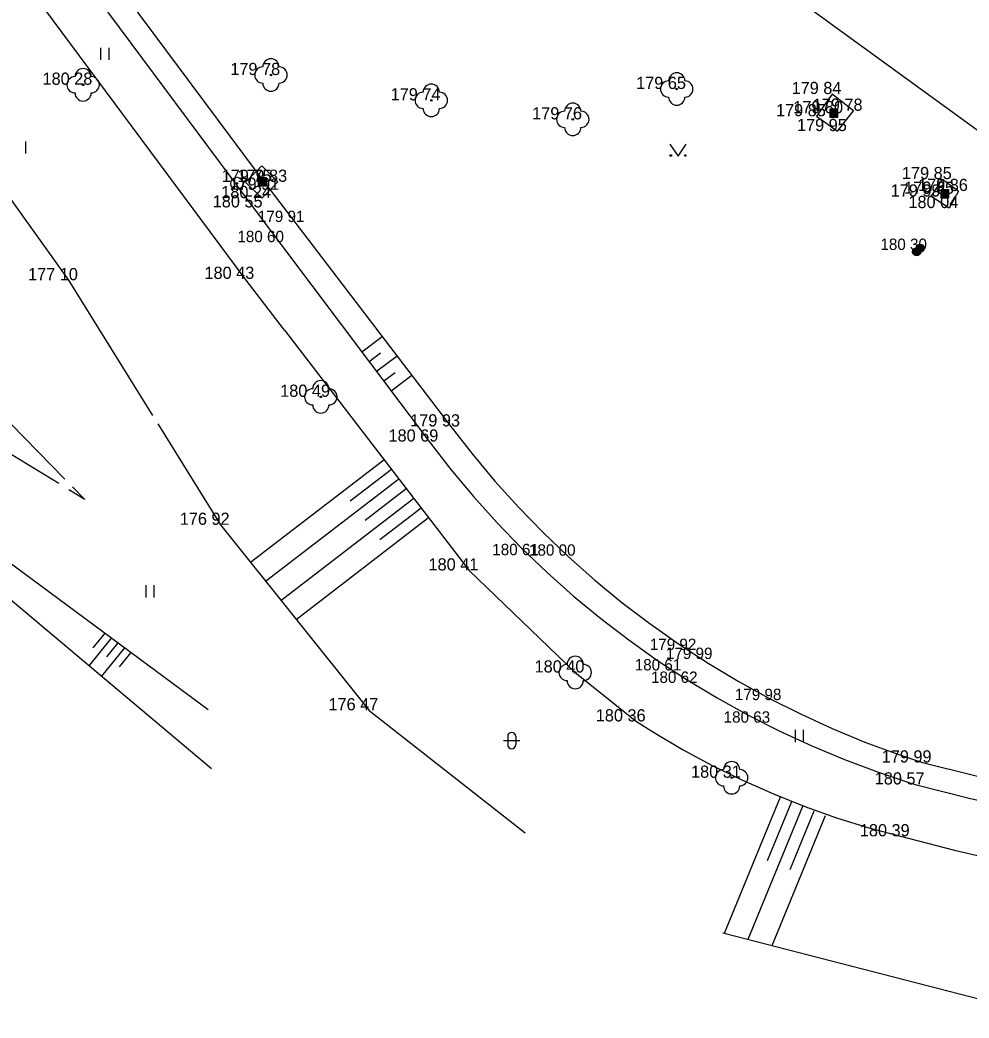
# Model space of a CAD drawing. Extents: x -537755 to -537431, y -1180722 to -1180510.
# Drawn here: x -537587.3 to -537528.9, y -1180712.7 to -1180651.3 of the extents above; entities that cross this region are included whole.
import ezdxf

# ---------------------------------------------------------------- set-up
doc = ezdxf.new("R2010")
doc.units = 0
for name, color, linetype in [('Vrstva 1', 7, 'Continuous'), ('Vrstva 11', 7, 'Continuous'), ('Vrstva 14', 7, 'Continuous'), ('Vrstva 15', 7, 'Continuous'), ('Vrstva 21', 7, 'Continuous'), ('Vrstva 22', 7, 'Continuous'), ('Vrstva 25', 7, 'Continuous'), ('Vrstva 3', 7, 'Continuous'), ('Vrstva 36', 7, 'Continuous'), ('Vrstva 4', 7, 'Continuous'), ('Vrstva 7', 7, 'Continuous')]:
    doc.layers.add(name, color=color, linetype=linetype)

msp = doc.modelspace()

# ---------------------------------------------------------------- linework, layer by layer
at = {"layer": 'Vrstva 1'}
for p, q in [((-537571.83, -1180654.66), (-537571.83, -1180654.66)), ((-537583.39, -1180655.26), (-537583.39, -1180655.26)), ((-537546.85, -1180655.52), (-537546.85, -1180655.52)), ((-537537.28, -1180655.83), (-537537.28, -1180655.83)), ((-537561.96, -1180656.22), (-537561.96, -1180656.22)), ((-537537.18, -1180657.01), (-537537.18, -1180657.01)), ((-537537.17, -1180657.03), (-537537.17, -1180657.03)), ((-537537.16, -1180657.03), (-537537.16, -1180657.03)), ((-537535.98, -1180656.86), (-537535.98, -1180656.86)), ((-537553.25, -1180657.39), (-537553.25, -1180657.39)), ((-537538.24, -1180657.2), (-537538.24, -1180657.2)), ((-537536.95, -1180658.11), (-537536.95, -1180658.11)), ((-537572.4, -1180661.25), (-537572.4, -1180661.25)), ((-537572.38, -1180661.27), (-537572.38, -1180661.27)), ((-537572.36, -1180661.24), (-537572.36, -1180661.24)), ((-537571.4, -1180661.235), (-537571.4, -1180661.235)), ((-537530.49, -1180661.07), (-537530.49, -1180661.07)), ((-537571.885, -1180661.727), (-537571.885, -1180661.727)), ((-537530.35, -1180661.97), (-537530.35, -1180661.97)), ((-537530.34, -1180661.92), (-537530.34, -1180661.92)), ((-537530.34, -1180661.97), (-537530.34, -1180661.97)), ((-537529.5, -1180661.8), (-537529.5, -1180661.8)), ((-537572.388, -1180662.237), (-537572.388, -1180662.237)), ((-537531.18, -1180662.14), (-537531.18, -1180662.14)), ((-537572.913, -1180662.812), (-537572.913, -1180662.812)), ((-537530.09, -1180662.85), (-537530.09, -1180662.85)), ((-537570.3, -1180663.71), (-537570.3, -1180663.71)), ((-537571.56, -1180664.95), (-537571.56, -1180664.95)), ((-537531.98, -1180665.43), (-537531.98, -1180665.43)), ((-537531.98, -1180665.45), (-537531.98, -1180665.45)), ((-537531.98, -1180665.53), (-537531.98, -1180665.53)), ((-537531.94, -1180665.49), (-537531.94, -1180665.49)), ((-537584.28, -1180667.29), (-537584.28, -1180667.29)), ((-537573.42, -1180667.21), (-537573.42, -1180667.21)), ((-537568.76, -1180674.47), (-537568.76, -1180674.47)), ((-537560.758, -1180676.295), (-537560.758, -1180676.295)), ((-537562.094, -1180677.223), (-537562.094, -1180677.223)), ((-537583.28, -1180680.79), (-537583.28, -1180680.79)), ((-537574.94, -1180682.35), (-537574.94, -1180682.35)), ((-537555.87, -1180684.22), (-537555.87, -1180684.22)), ((-537553.61, -1180684.25), (-537553.61, -1180684.25)), ((-537559.63, -1180685.16), (-537559.63, -1180685.16)), ((-537546.176, -1180690.057), (-537546.176, -1180690.057)), ((-537545.18, -1180690.61), (-537545.18, -1180690.61)), ((-537553.1, -1180691.44), (-537553.1, -1180691.44)), ((-537547.103, -1180691.315), (-537547.103, -1180691.315)), ((-537546.1, -1180692.08), (-537546.1, -1180692.08)), ((-537540.94, -1180693.14), (-537540.94, -1180693.14)), ((-537565.79, -1180693.77), (-537565.79, -1180693.77)), ((-537549.334, -1180694.452), (-537549.334, -1180694.452)), ((-537541.63, -1180694.53), (-537541.63, -1180694.53)), ((-537547.66, -1180695.08), (-537547.66, -1180695.08)), ((-537531.733, -1180696.981), (-537531.733, -1180696.981)), ((-537543.47, -1180697.92), (-537543.47, -1180697.92)), ((-537532.164, -1180698.334), (-537532.164, -1180698.334)), ((-537539.05, -1180699.72), (-537539.05, -1180699.72)), ((-537533.08, -1180701.525), (-537533.08, -1180701.525))]:
    msp.add_line(p, q, dxfattribs=at)
at = {"layer": 'Vrstva 11'}
msp.add_line((-537543.39, -1180647.11), (-537522, -1180662.66), dxfattribs=at)
msp.add_lwpolyline([(-537572.388, -1180662.237), (-537571.885, -1180661.727), (-537571.4, -1180661.235), (-537572.397, -1180660.252), (-537572.732, -1180660.592), (-537573.385, -1180661.254), (-537572.388, -1180662.237)], dxfattribs=at)
at = {"layer": 'Vrstva 14'}
for p, q in [((-537573.42, -1180667.21), (-537593.09, -1180640.69)), ((-537583.28, -1180646.46), (-537572.732, -1180660.592)), ((-537584.444, -1180647.34), (-537572.913, -1180662.812)), ((-537594.91, -1180652.5), (-537584.28, -1180667.29)), ((-537572.732, -1180660.592), (-537571.885, -1180661.727)), ((-537571.885, -1180661.727), (-537560.758, -1180676.295)), ((-537572.913, -1180662.812), (-537562.094, -1180677.223)), ((-537584.28, -1180667.29), (-537579.119, -1180675.612)), ((-537570.989, -1180670.374), (-537573.42, -1180667.21)), ((-537593.74, -1180670.11), (-537584.511, -1180679.533)), ((-537570.989, -1180670.374), (-537559.63, -1180685.16)), ((-537584.89, -1180679.808), (-537598.82, -1180671.31)), ((-537578.792, -1180676.139), (-537574.94, -1180682.35)), ((-537583.28, -1180680.79), (-537584.269, -1180680.186)), ((-537584.038, -1180680.016), (-537583.28, -1180680.79)), ((-537574.94, -1180682.35), (-537565.79, -1180693.77)), ((-537592.06, -1180683.41), (-537575.48, -1180697.36)), ((-537575.7, -1180693.73), (-537588.89, -1180683.98)), ((-537548.506, -1180688.433), (-537546.738, -1180689.681)), ((-537549.805, -1180689.438), (-537548.031, -1180690.695)), ((-537565.79, -1180693.77), (-537556.18, -1180701.31)), ((-537539.242, -1180693.992), (-537537.275, -1180694.893)), ((-537540.513, -1180695.047), (-537538.54, -1180695.958)), ((-537535.03, -1180700.998), (-537533.08, -1180701.525)), ((-537544.01, -1180707.46), (-537523.671, -1180712.712))]:
    msp.add_line(p, q, dxfattribs=at)
for points in [[(-537560.758, -1180676.295), (-537559.43, -1180678.003), (-537558.04, -1180679.662), (-537556.59, -1180681.267), (-537555.082, -1180682.818)], [(-537562.094, -1180677.223), (-537560.762, -1180678.941), (-537559.368, -1180680.608), (-537557.913, -1180682.223), (-537556.4, -1180683.783)], [(-537555.082, -1180682.818), (-537553.517, -1180684.312), (-537551.898, -1180685.747), (-537550.227, -1180687.122), (-537548.506, -1180688.433)], [(-537556.4, -1180683.783), (-537554.83, -1180685.287), (-537553.206, -1180686.732), (-537551.53, -1180688.116), (-537549.805, -1180689.438)], [(-537559.63, -1180685.16), (-537553.1, -1180691.44)], [(-537546.738, -1180689.681), (-537544.925, -1180690.862), (-537543.07, -1180691.975), (-537541.175, -1180693.019), (-537539.242, -1180693.992)], [(-537548.031, -1180690.695), (-537546.213, -1180691.886), (-537544.352, -1180693.009), (-537542.452, -1180694.063), (-537540.513, -1180695.047)], [(-537553.1, -1180691.44), (-537549.334, -1180694.452)], [(-537549.334, -1180694.452), (-537548.275, -1180695.122), (-537546.487, -1180696.177), (-537544.66, -1180697.163), (-537542.796, -1180698.077)], [(-537537.275, -1180694.893), (-537535.276, -1180695.72), (-537533.248, -1180696.473), (-537531.733, -1180696.981)], [(-537538.54, -1180695.958), (-537536.534, -1180696.797), (-537534.499, -1180697.56), (-537532.438, -1180698.249), (-537532.164, -1180698.334)], [(-537531.733, -1180696.981), (-537528.51, -1180697.785), (-537525.268, -1180698.511), (-537522.01, -1180699.158)], [(-537542.796, -1180698.077), (-537540.898, -1180698.919), (-537538.969, -1180699.687), (-537537.012, -1180700.381), (-537535.03, -1180700.998)], [(-537532.164, -1180698.334), (-537528.761, -1180699.188), (-537525.339, -1180699.965)], [(-537533.08, -1180701.525), (-537529.747, -1180702.38), (-537526.396, -1180703.158)]]:
    msp.add_lwpolyline(points, dxfattribs=at)
at = {"layer": 'Vrstva 15'}
for p, q in [((-537564.975, -1180670.773), (-537566.229, -1180671.715)), ((-537565.079, -1180671.79), (-537565.779, -1180672.315)), ((-537564.065, -1180671.966), (-537565.329, -1180672.914)), ((-537564.179, -1180672.989), (-537564.878, -1180673.514)), ((-537563.154, -1180673.158), (-537564.428, -1180674.114)), ((-537573.092, -1180684.656), (-537564.87, -1180678.339)), ((-537566.948, -1180680.88), (-537564.413, -1180678.933)), ((-537572.154, -1180685.827), (-537563.956, -1180679.528)), ((-537566.033, -1180682.07), (-537563.499, -1180680.123)), ((-537571.216, -1180686.998), (-537563.042, -1180680.718)), ((-537565.12, -1180683.26), (-537562.585, -1180681.312)), ((-537570.278, -1180688.168), (-537562.129, -1180681.907)), ((-537582.06, -1180689.029), (-537582.785, -1180689.923)), ((-537581.659, -1180689.325), (-537583.025, -1180691.012)), ((-537581.256, -1180689.623), (-537581.941, -1180690.468)), ((-537580.853, -1180689.921), (-537582.259, -1180691.656)), ((-537580.452, -1180690.218), (-537581.166, -1180691.1)), ((-537543.914, -1180707.485), (-537540.469, -1180699.097)), ((-537541.263, -1180703.005), (-537539.776, -1180699.382)), ((-537542.448, -1180707.863), (-537539.082, -1180699.667)), ((-537539.876, -1180703.575), (-537538.388, -1180699.952)), ((-537540.982, -1180708.242), (-537537.694, -1180700.237))]:
    msp.add_line(p, q, dxfattribs=at)
at = {"layer": 'Vrstva 21'}
for radius in [0.375, 0.05]:
    msp.add_circle((-537573.93, -1180661.33), radius, dxfattribs=at)
at = {"layer": 'Vrstva 22'}
for centre in [(-537571.83, -1180654.66), (-537583.39, -1180655.26), (-537546.85, -1180655.52), (-537561.96, -1180656.22), (-537553.25, -1180657.39), (-537568.76, -1180674.47), (-537553.1, -1180691.44), (-537543.47, -1180697.92)]:
    msp.add_circle(centre, 0.05, dxfattribs=at)
for centre, start, end in [((-537571.83, -1180654.16), 0, 180), ((-537583.39, -1180654.76), 0, 180), ((-537572.33, -1180654.66), 90, 270), ((-537571.33, -1180654.66), 270, 90), ((-537546.85, -1180655.02), 0, 180), ((-537583.89, -1180655.26), 90, 270), ((-537582.89, -1180655.26), 270, 90), ((-537571.83, -1180655.16), 180, 0), ((-537561.96, -1180655.72), 0, 180), ((-537547.35, -1180655.52), 90, 270), ((-537546.35, -1180655.52), 270, 90), ((-537583.39, -1180655.76), 180, 0), ((-537562.46, -1180656.22), 90, 270), ((-537561.46, -1180656.22), 270, 90), ((-537553.25, -1180656.89), 0, 180), ((-537546.85, -1180656.02), 180, 0), ((-537561.96, -1180656.72), 180, 0), ((-537553.75, -1180657.39), 90, 270), ((-537552.75, -1180657.39), 270, 90), ((-537553.25, -1180657.89), 180, 0), ((-537568.76, -1180673.97), 0, 180), ((-537569.26, -1180674.47), 90, 270), ((-537568.26, -1180674.47), 270, 90), ((-537568.76, -1180674.97), 180, 0), ((-537553.6, -1180691.44), 90, 270), ((-537553.1, -1180690.94), 0, 180), ((-537552.6, -1180691.44), 270, 90), ((-537553.1, -1180691.94), 180, 0), ((-537543.47, -1180697.42), 0, 180), ((-537543.97, -1180697.92), 90, 270), ((-537542.97, -1180697.92), 270, 90), ((-537543.47, -1180698.42), 180, 0)]:
    msp.add_arc(centre, 0.5, start, end, dxfattribs=at)
at = {"layer": 'Vrstva 25'}
for points in [[(-537537.43, -1180657.26), (-537536.93, -1180657.26), (-537536.93, -1180656.76), (-537537.43, -1180656.76)], [(-537537.38, -1180657.21), (-537536.98, -1180657.21), (-537536.98, -1180656.81), (-537537.38, -1180656.81)], [(-537537.33, -1180657.16), (-537537.03, -1180657.16), (-537537.03, -1180656.86), (-537537.33, -1180656.86)], [(-537537.28, -1180657.11), (-537537.08, -1180657.11), (-537537.08, -1180656.91), (-537537.28, -1180656.91)], [(-537537.23, -1180657.06), (-537537.13, -1180657.06), (-537537.13, -1180656.96), (-537537.23, -1180656.96)], [(-537572.61, -1180661.49), (-537572.11, -1180661.49), (-537572.11, -1180660.99), (-537572.61, -1180660.99)], [(-537572.56, -1180661.44), (-537572.16, -1180661.44), (-537572.16, -1180661.04), (-537572.56, -1180661.04)], [(-537572.51, -1180661.39), (-537572.21, -1180661.39), (-537572.21, -1180661.09), (-537572.51, -1180661.09)], [(-537572.46, -1180661.34), (-537572.26, -1180661.34), (-537572.26, -1180661.14), (-537572.46, -1180661.14)], [(-537572.41, -1180661.29), (-537572.31, -1180661.29), (-537572.31, -1180661.19), (-537572.41, -1180661.19)], [(-537530.6, -1180662.22), (-537530.1, -1180662.22), (-537530.1, -1180661.72), (-537530.6, -1180661.72)], [(-537530.55, -1180662.17), (-537530.15, -1180662.17), (-537530.15, -1180661.77), (-537530.55, -1180661.77)], [(-537530.5, -1180662.12), (-537530.2, -1180662.12), (-537530.2, -1180661.82), (-537530.5, -1180661.82)], [(-537530.45, -1180662.07), (-537530.25, -1180662.07), (-537530.25, -1180661.87), (-537530.45, -1180661.87)], [(-537530.4, -1180662.02), (-537530.3, -1180662.02), (-537530.3, -1180661.92), (-537530.4, -1180661.92)]]:
    msp.add_lwpolyline(points, close=True, dxfattribs=at)
for centre, radius in [((-537531.87, -1180665.32), 0.25), ((-537531.87, -1180665.32), 0.2), ((-537532.08, -1180665.54), 0.25), ((-537532.08, -1180665.54), 0.2), ((-537532.08, -1180665.54), 0.15), ((-537532.08, -1180665.54), 0.1), ((-537532.08, -1180665.54), 0.05), ((-537531.87, -1180665.32), 0.15), ((-537531.87, -1180665.32), 0.1), ((-537531.87, -1180665.32), 0.05)]:
    msp.add_circle(centre, radius, dxfattribs=at)
at = {"layer": 'Vrstva 36'}
for p, q in [((-537582.293, -1180653.732), (-537582.293, -1180652.982)), ((-537581.793, -1180653.732), (-537581.793, -1180652.982)), ((-537586.914, -1180659.495), (-537586.914, -1180658.745)), ((-537579.519, -1180686.817), (-537579.519, -1180686.067)), ((-537579.019, -1180686.817), (-537579.019, -1180686.067)), ((-537539.539, -1180695.727), (-537539.539, -1180694.977)), ((-537539.039, -1180695.727), (-537539.039, -1180694.977)), ((-537557.507, -1180695.63), (-537556.507, -1180695.63)), ((-537557.257, -1180695.38), (-537557.257, -1180695.88)), ((-537556.757, -1180695.38), (-537556.757, -1180695.88))]:
    msp.add_line(p, q, dxfattribs=at)
msp.add_lwpolyline([(-537547.267, -1180658.915), (-537546.767, -1180659.665), (-537546.267, -1180658.915)], dxfattribs=at)
for centre in [(-537547.217, -1180659.615), (-537546.318, -1180659.615)]:
    msp.add_circle(centre, 0.05, dxfattribs=at)
for centre, start, end in [((-537557.007, -1180695.38), 0, 180), ((-537557.007, -1180695.88), 180, 0)]:
    msp.add_arc(centre, 0.25, start, end, dxfattribs=at)
at = {"layer": 'Vrstva 7'}
for points in [[(-537536.95, -1180658.11), (-537535.98, -1180656.86), (-537537.28, -1180655.83), (-537538.24, -1180657.2), (-537536.95, -1180658.11)], [(-537530.49, -1180661.07), (-537529.5, -1180661.8), (-537530.09, -1180662.85), (-537531.18, -1180662.14), (-537530.49, -1180661.07)]]:
    msp.add_lwpolyline(points, dxfattribs=at)

# ---------------------------------------------------------------- texts
at = {"layer": 'Vrstva 3'}
for s, height, p in [('179 78 ', 0.75, (-537574.33, -1180654.66)), ('180 28 ', 0.75, (-537585.89, -1180655.26)), ('179 65 ', 0.75, (-537549.35, -1180655.52)), ('179 84 ', 0.75, (-537539.78, -1180655.83)), ('179 74 ', 0.75, (-537564.46, -1180656.22)), ('179 85 ', 0.75, (-537540.74, -1180657.2)), ('179 80 ', 0.75, (-537539.68, -1180657.01)), ('179 78 ', 0.75, (-537538.48, -1180656.86)), ('179 76 ', 0.75, (-537555.75, -1180657.39)), ('179 95 ', 0.75, (-537539.45, -1180658.11)), ('179 75 ', 0.75, (-537574.859, -1180661.24)), ('179 85 ', 0.75, (-537532.99, -1180661.07)), ('179 99 ', 0.75, (-537533.68, -1180662.14)), ('179 85 ', 0.75, (-537532.849, -1180661.97)), ('179 86 ', 0.75, (-537532, -1180661.8)), ('180 04 ', 0.75, (-537532.59, -1180662.85)), ('179 91 ', 0.7, (-537572.633, -1180663.71)), ('180 30 ', 0.7, (-537534.313, -1180665.43)), ('177 10 ', 0.75, (-537586.78, -1180667.29)), ('180 43 ', 0.75, (-537575.92, -1180667.21)), ('180 49 ', 0.75, (-537571.26, -1180674.47)), ('179 93 ', 0.75, (-537563.258, -1180676.295)), ('180 69 ', 0.75, (-537564.594, -1180677.223)), ('176 92 ', 0.75, (-537577.44, -1180682.35)), ('180 61 ', 0.7, (-537558.203, -1180684.22)), ('180 00 ', 0.7, (-537555.943, -1180684.25)), ('180 41 ', 0.75, (-537562.13, -1180685.16)), ('179 92 ', 0.7, (-537548.509, -1180690.057)), ('179 99 ', 0.7, (-537547.513, -1180690.61)), ('180 40 ', 0.75, (-537555.6, -1180691.44)), ('180 61 ', 0.7, (-537549.436, -1180691.315)), ('180 62 ', 0.7, (-537548.433, -1180692.08)), ('179 98 ', 0.7, (-537543.273, -1180693.14)), ('176 47 ', 0.75, (-537568.29, -1180693.77)), ('180 36 ', 0.75, (-537551.834, -1180694.452)), ('180 63 ', 0.7, (-537543.963, -1180694.53)), ('179 99 ', 0.75, (-537534.233, -1180696.981)), ('180 31 ', 0.75, (-537545.97, -1180697.92)), ('180 57 ', 0.75, (-537534.664, -1180698.334)), ('180 39 ', 0.75, (-537535.58, -1180701.525))]:
    msp.add_text(s, height=height, dxfattribs=at).set_placement(p)
at = {"layer": 'Vrstva 4'}
for s, height, p in [('179 83 ', 0.75, (-537573.9, -1180661.235)), ('179 91 ', 0.75, (-537574.385, -1180661.727)), ('180 55 ', 0.75, (-537575.413, -1180662.812)), ('180 24 ', 0.75, (-537574.888, -1180662.237)), ('180 60 ', 0.7, (-537573.893, -1180664.95))]:
    msp.add_text(s, height=height, dxfattribs=at).set_placement(p)

doc.saveas('drawing.dxf')
